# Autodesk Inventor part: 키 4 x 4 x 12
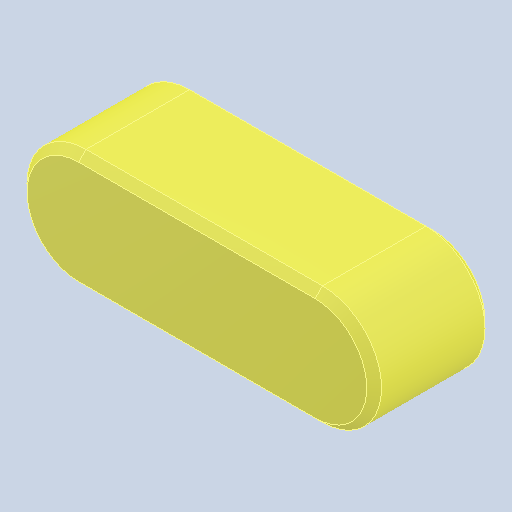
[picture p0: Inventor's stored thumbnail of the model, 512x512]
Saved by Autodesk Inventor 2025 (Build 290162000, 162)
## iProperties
Created: 2024-07
Part Number: 키 4 x 4 x 12
Material: 강철, 연강
Description: 키 및 해당 키홈
Document SubType Name: Modeling
Designer: myung
Density: 7.85 g/cm^3
Appearance: 기본값
Author: jhkim
Sending System: Autodesk Inventor 2025
Preprocessor: ST-DEVELOPER v20
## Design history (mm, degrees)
feature "Solid1"
node "솔리드1"
